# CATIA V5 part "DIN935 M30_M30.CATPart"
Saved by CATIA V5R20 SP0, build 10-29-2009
Part number: DIN935 M30_M30
Revision: ANY
Definition: UNKNOWN
Nomenclature: DIN935 M30_M30
Source: Unknown
Bounding box of the stored display mesh (mm): x -23 to 23, y -26.558 to 26.558, z 0 to 33
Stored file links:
  C:\Users\Utente\Desktop\IO LAVORO\3D X SITO CF\X 3D SITO CF 27-09-2020\740T\740T-30\DIN935 M30_M30.CATPart
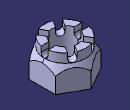
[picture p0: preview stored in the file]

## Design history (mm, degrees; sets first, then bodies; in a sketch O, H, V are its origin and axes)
Body1 "NONE" (main body)
  Solid1: solid without history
